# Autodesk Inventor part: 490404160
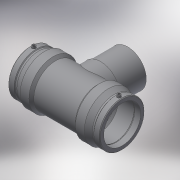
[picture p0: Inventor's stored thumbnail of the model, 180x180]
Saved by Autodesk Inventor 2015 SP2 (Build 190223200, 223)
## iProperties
Created: 2017-06
Part Number: 490404160
Material: Generic
Description: PLASSON TEE 160-160-160
Document SubType Name: Modeling
Designer: KIM
Mass: 5399.73 g
Surface Area: 5772.21 cm^2
Volume: 5399.73 cm^3
Density: 1 g/cm^3
Appearance: Default
Author: KIM
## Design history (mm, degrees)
derived "490404.ipt"
feature "Solid1::490404.ipt"
tag "TaggingFeature1"
body "Solid1"
other parameters: "d0" = 396, "d2" = 209, "d3" = 97, "d4" = 99, "d5" = 188.1, "d6" = 152, "d8" = 168 deg, "d10" = 38.8, "d11" = 12.93333, "d13" = 396, "d14" = 17.6296, "d17" = 144, "d19" = 3.52592, "d20" = 168 deg, "d22" = 194.37, "d23" = 209, "d24" = 188.5389, "d25" = 135 deg, "d26" = 277.2, "d27" = 135 deg, "d29" = 105, "d30" = 15, "d31" = 158.4, "d34" = 5 deg, "d35" = 15, "d39" = 5 deg, "d40" = 9.6, "d41" = 4.8, "d42" = 6, "d43" = 0, "d45" = 4, "d46" = 14, "d47" = 0, "d48" = -222, "d51" = 0, "d52" = 128, "d54" = 0, "d55" = 188.1, "d56" = 209, "d57" = 138.6, "d58" = 135 deg, "d59" = 97, "d60" = 97, "d61" = 135 deg, "d62" = 222, "d72" = 180.18, "d73" = 90.09, "d74" = -222, "d75" = 168, "d77" = 0, "d78" = 128, "d80" = 0, "d82" = 117.5, "d83" = 0, "d84" = 3, "d85" = 0, "d86" = 3, "d87" = 0, "d88" = 28.13, "d89" = 7.0325, "d90" = 28.13, "L_" = 396, "L_1" = 97, "D_" = 209, "A_" = 105, "d_2" = 12, "H_" = 222
